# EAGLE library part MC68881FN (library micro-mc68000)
68xxx PROCESSOR
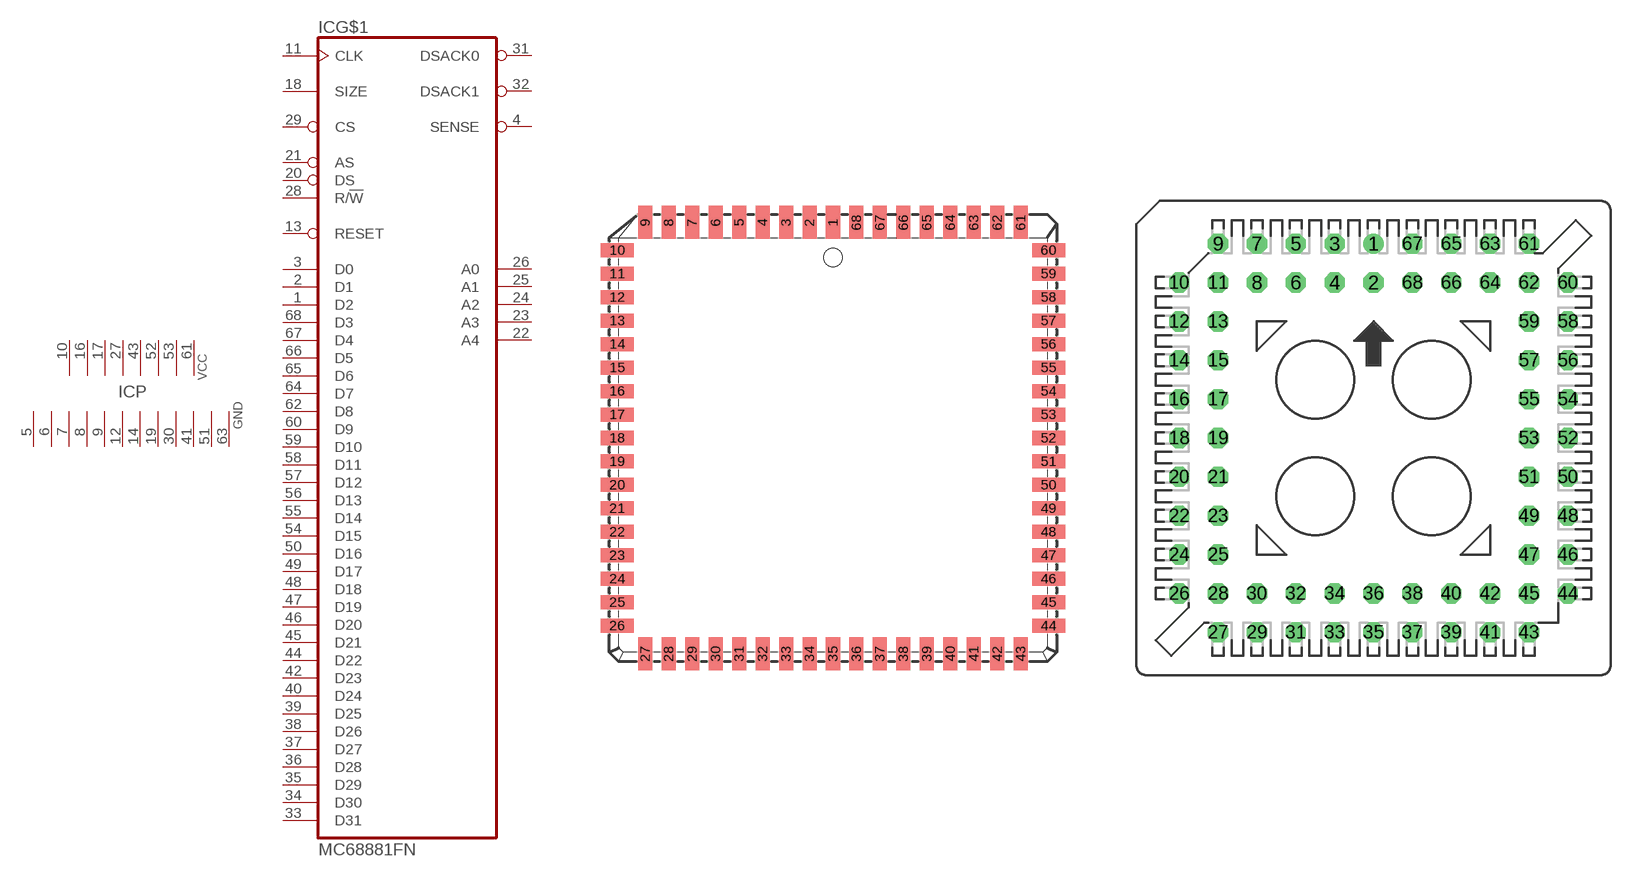
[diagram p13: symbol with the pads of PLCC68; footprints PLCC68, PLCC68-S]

Designator prefix IC; gates G$1=68881 P=8PWR12GN

## MC68881FN (OC_FARNELL: unknown; OC_NEWARK: unknown)  [PLCC68]
1  G$1:D2
2  G$1:D1
3  G$1:D0
4  G$1:SENSE
5  P:GND  pwr
6  P:GND  pwr
7  P:GND  pwr
8  P:GND  pwr
9  P:GND  pwr
10  P:VCC  pwr
11  G$1:CLK  in
12  P:GND  pwr
13  G$1:RESET  in
14  P:GND  pwr
16  P:VCC  pwr
17  P:VCC  pwr
18  G$1:SIZE  in
19  P:GND  pwr
20  G$1:DS  in
21  G$1:AS  in
22  G$1:A4  in
23  G$1:A3  in
24  G$1:A2  in
25  G$1:A1  in
26  G$1:A0  in
27  P:VCC  pwr
28  G$1:R/!W  in
29  G$1:CS  in
30  P:GND  pwr
31  G$1:DSACK0  out
32  G$1:DSACK1  out
33  G$1:D31
34  G$1:D30
35  G$1:D29
36  G$1:D28
37  G$1:D27
38  G$1:D26
39  G$1:D25
40  G$1:D24
41  P:GND  pwr
42  G$1:D23
43  P:VCC  pwr
44  G$1:D22
45  G$1:D21
46  G$1:D20
47  G$1:D19
48  G$1:D18
49  G$1:D17
50  G$1:D16
51  P:GND  pwr
52  P:VCC  pwr
53  P:VCC  pwr
54  G$1:D15
55  G$1:D14
56  G$1:D13
57  G$1:D12
58  G$1:D11
59  G$1:D10
60  G$1:D9
61  P:VCC  pwr
62  G$1:D8
63  P:GND  pwr
64  G$1:D7
65  G$1:D6
66  G$1:D5
67  G$1:D4
68  G$1:D3

## MC68881FN-SOC (OC_FARNELL: unknown; OC_NEWARK: unknown)  [PLCC68-S]
Pads as for PLCC68

## Footprint PLCC68 (pad centres in mm)
PLASTIC LEADED CHIP CARRIER square
smd 0.76 x 1.8: 1 0,11.67; 2 -1.27,11.67; 3 -2.54,11.67; 4 -3.81,11.67; 5 -5.08,11.67; 6 -6.35,11.67; 7 -7.62,11.67; 8 -8.89,11.67; 9 -10.16,11.67; 27 -10.16,-11.67; 28 -8.89,-11.67; 29 -7.62,-11.67; 30 -6.35,-11.67; 31 -5.08,-11.67; 32 -3.81,-11.67; 33 -2.54,-11.67; 34 -1.27,-11.67; 35 0,-11.67; 36 1.27,-11.67; 37 2.54,-11.67; 38 3.81,-11.67; 39 5.08,-11.67; 40 6.35,-11.67; 41 7.62,-11.67; 42 8.89,-11.67; 43 10.16,-11.67; 61 10.16,11.67; 62 8.89,11.67; 63 7.62,11.67; 64 6.35,11.67; 65 5.08,11.67; 66 3.81,11.67; 67 2.54,11.67; 68 1.27,11.67
smd 1.8 x 0.76: 10 -11.67,10.16; 11 -11.67,8.89; 12 -11.67,7.62; 13 -11.67,6.35; 14 -11.67,5.08; 15 -11.67,3.81; 16 -11.67,2.54; 17 -11.67,1.27; 18 -11.67,0; 19 -11.67,-1.27; 20 -11.67,-2.54; 21 -11.67,-3.81; 22 -11.67,-5.08; 23 -11.67,-6.35; 24 -11.67,-7.62; 25 -11.67,-8.89; 26 -11.67,-10.16; 44 11.67,-10.16; 45 11.67,-8.89; 46 11.67,-7.62; 47 11.67,-6.35; 48 11.67,-5.08; 49 11.67,-3.81; 50 11.67,-2.54; 51 11.67,-1.27; 52 11.67,0; 53 11.67,1.27; 54 11.67,2.54; 55 11.67,3.81; 56 11.67,5.08; 57 11.67,6.35; 58 11.67,7.62; 59 11.67,8.89; 60 11.67,10.16

## Footprint PLCC68-S (pad centres in mm)
PLCC Socked
drill 0.813 round: 1 0,12.7
drill 0.813 octagon: 2 0,10.16; 3 -2.54,12.7; 4 -2.54,10.16; 5 -5.08,12.7; 6 -5.08,10.16; 7 -7.62,12.7; 8 -7.62,10.16; 9 -10.16,12.7; 10 -12.7,10.16; 11 -10.16,10.16; 12 -12.7,7.62; 13 -10.16,7.62; 14 -12.7,5.08; 15 -10.16,5.08; 16 -12.7,2.54; 17 -10.16,2.54; 18 -12.7,0; 19 -10.16,0; 20 -12.7,-2.54; 21 -10.16,-2.54; 22 -12.7,-5.08; 23 -10.16,-5.08; 24 -12.7,-7.62; 25 -10.16,-7.62; 26 -12.7,-10.16; 27 -10.16,-12.7; 28 -10.16,-10.16; 29 -7.62,-12.7; 30 -7.62,-10.16; 31 -5.08,-12.7; 32 -5.08,-10.16; 33 -2.54,-12.7; 34 -2.54,-10.16; 35 0,-12.7; 36 0,-10.16; 37 2.54,-12.7; 38 2.54,-10.16; 39 5.08,-12.7; 40 5.08,-10.16; 41 7.62,-12.7; 42 7.62,-10.16; 43 10.16,-12.7; 44 12.7,-10.16; 45 10.16,-10.16; 46 12.7,-7.62; 47 10.16,-7.62; 48 12.7,-5.08; 49 10.16,-5.08; 50 12.7,-2.54; 51 10.16,-2.54; 52 12.7,0; 53 10.16,0; 54 12.7,2.54; 55 10.16,2.54; 56 12.7,5.08; 57 10.16,5.08; 58 12.7,7.62; 59 10.16,7.62; 60 12.7,10.16; 61 10.16,12.7; 62 10.16,10.16; 63 7.62,12.7; 64 7.62,10.16; 65 5.08,12.7; 66 5.08,10.16; 67 2.54,12.7; 68 2.54,10.16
